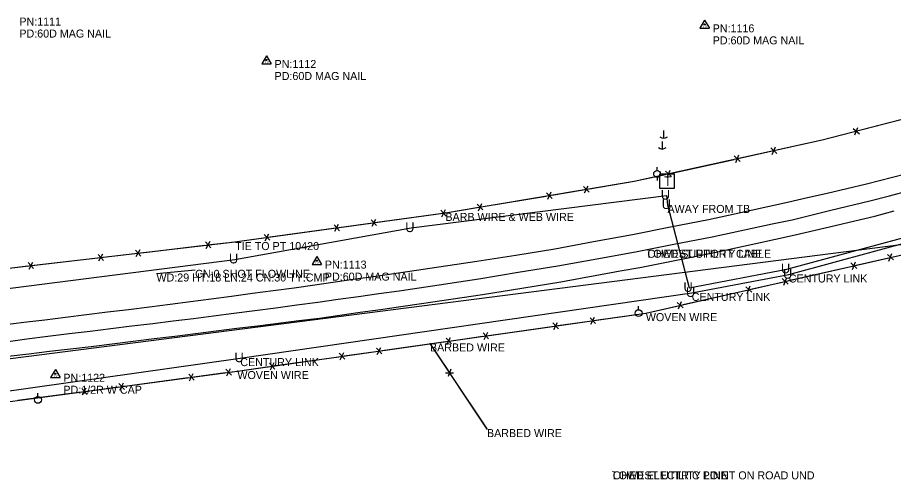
# Model space of a CAD drawing. Extents: x 1568433 to 1572450, y 731863 to 733450.
# Drawn here: x 1570751 to 1571298, y 732188 to 732476 of the extents above; entities that cross this region are included whole.
import ezdxf

# ---------------------------------------------------------------- set-up
doc = ezdxf.new("R2010")
doc.units = 0
for name, color, linetype in [('Default', 7, 'Continuous'), ('S_BASELINE', 7, 'Continuous'), ('S_CROSS_DRAIN', 7, 'Continuous'), ('S_CROSS_DRAIN_ANNOT', 7, 'Continuous'), ('S_DRG_PT_SYM', 7, 'Continuous'), ('S_EDGE_PAVEMENT', 7, 'Continuous'), ('S_ELECTRIC_UTILITIES_ANNOT', 7, 'Continuous'), ('S_FENCE', 7, 'Continuous'), ('S_FENCE_ANNOT', 7, 'Continuous'), ('S_MSC_PT_SYM', 7, 'Continuous'), ('S_PAVEMENT_CROWN', 7, 'Continuous'), ('S_SECONDARY_CTL', 7, 'Continuous'), ('S_SECONDARY_CTL_ANNOT', 7, 'Continuous'), ('S_SURVEY_TEXT_ANNOT', 7, 'Continuous'), ('S_TELEPHONE_UTILITIES', 7, 'Continuous'), ('S_UNDERGROUND_CABLE', 7, 'Continuous'), ('S_UNDERGROUND_CABLE_ANNOT', 7, 'Continuous'), ('S_UTILITY_POLE', 7, 'Continuous'), ('S_UTL_PT_SYM', 7, 'Continuous')]:
    doc.layers.add(name, color=color, linetype=linetype)

msp = doc.modelspace()

# ---------------------------------------------------------------- linework, layer by layer
at = {"layer": 'S_BASELINE'}
msp.add_line((1570488.07, 732230.45), (1571317.07, 732336.49), dxfattribs=at)
at = {"layer": 'S_CROSS_DRAIN'}
msp.add_line((1570837.86, 732316.62), (1570862.03, 732318.92), dxfattribs=at)
at = {"layer": 'S_DRG_PT_SYM'}
for points in [[(1570837.86, 732316.62), (1570837.86, 732316.67), (1570837.86, 732316.62), (1570837.81, 732316.62), (1570837.86, 732316.62), (1570837.86, 732316.57), (1570837.86, 732316.62), (1570837.91, 732316.62)], [(1570862.03, 732318.92), (1570862.03, 732318.97), (1570862.03, 732318.92), (1570861.98, 732318.92), (1570862.03, 732318.92), (1570862.03, 732318.87), (1570862.03, 732318.92), (1570862.08, 732318.92)]]:
    msp.add_lwpolyline(points, dxfattribs=at)
at = {"layer": 'S_EDGE_PAVEMENT'}
for points in [[(1570742.1, 732284.58), (1570755.11, 732286.19), (1570768.12, 732287.8), (1570781.13, 732289.41), (1570794.24, 732291.03), (1570807.35, 732292.64), (1570820.46, 732294.25), (1570833.57, 732295.86), (1570846.36, 732297.54), (1570859.16, 732299.21), (1570871.96, 732300.88), (1570884.76, 732302.56), (1570897.75, 732304.29), (1570910.75, 732306.02), (1570923.75, 732307.75), (1570936.75, 732309.48), (1570949.47, 732311.34), (1570962.19, 732313.2), (1570974.92, 732315.05), (1570987.64, 732316.91), (1571000.2, 732318.74), (1571012.76, 732320.56), (1571025.32, 732322.38), (1571037.88, 732324.21), (1571062.21, 732328.15), (1571086.55, 732332.08), (1571110.84, 732336.56), (1571135.14, 732341.04), (1571158.87, 732345.69), (1571182.6, 732350.35), (1571194.93, 732353.04), (1571207.26, 732355.74), (1571219.6, 732358.44), (1571231.93, 732361.14), (1571244.27, 732363.99), (1571256.61, 732366.84), (1571268.95, 732369.68), (1571281.29, 732372.53), (1571305.48, 732378.73)], [(1570745.24, 732265.07), (1570758.2, 732266.55), (1570771.16, 732268.04), (1570784.12, 732269.52), (1570797.21, 732271.13), (1570810.29, 732272.75), (1570823.37, 732274.36), (1570836.45, 732275.97), (1570849.37, 732277.58), (1570862.3, 732279.19), (1570875.22, 732280.79), (1570888.14, 732282.4), (1570901, 732283.99), (1570913.87, 732285.58), (1570926.73, 732287.18), (1570939.59, 732288.77), (1570952.33, 732290.59), (1570965.07, 732292.41), (1570977.81, 732294.23), (1570990.54, 732296.06), (1571003.27, 732297.92), (1571016, 732299.78), (1571028.73, 732301.65), (1571041.46, 732303.51), (1571065.9, 732307.45), (1571090.34, 732311.39), (1571102.68, 732313.66), (1571115.01, 732315.92), (1571127.35, 732318.19), (1571139.68, 732320.46), (1571163.51, 732325.17), (1571187.33, 732329.87), (1571199.67, 732332.57), (1571212.01, 732335.27), (1571224.35, 732337.97), (1571236.69, 732340.67), (1571249.12, 732343.61), (1571261.55, 732346.56), (1571273.98, 732349.5), (1571286.41, 732352.44), (1571298.54, 732355.64)]]:
    msp.add_lwpolyline(points, dxfattribs=at)
at = {"layer": 'S_FENCE'}
for p, q in [((1571253.56, 732399.93), (1571367.97, 732429.81)), ((1571272.92, 732407.11), (1571276.73, 732403.87)), ((1571272.92, 732407.11), (1571276.73, 732403.87)), ((1571273.96, 732403.14), (1571275.69, 732407.83)), ((1571273.96, 732403.14), (1571275.69, 732407.83)), ((1571136.16, 732374.14), (1571253.56, 732399.93)), ((1571221.49, 732394.98), (1571225.16, 732391.6)), ((1571221.49, 732394.98), (1571225.16, 732391.6)), ((1571222.37, 732390.98), (1571224.28, 732395.6)), ((1571222.37, 732390.98), (1571224.28, 732395.6)), ((1571198.65, 732389.96), (1571202.32, 732386.58)), ((1571198.65, 732389.96), (1571202.32, 732386.58)), ((1571199.53, 732385.96), (1571201.44, 732390.58)), ((1571199.53, 732385.96), (1571201.44, 732390.58)), ((1571156.65, 732376.54), (1571158.56, 732381.16)), ((1571156.65, 732376.54), (1571158.56, 732381.16)), ((1571155.77, 732380.54), (1571159.44, 732377.15)), ((1571155.77, 732380.54), (1571159.44, 732377.15)), ((1571018.28, 732354.41), (1571136.16, 732374.14)), ((1571104.54, 732370.92), (1571108.04, 732367.35)), ((1571104.54, 732370.92), (1571108.04, 732367.35)), ((1571105.21, 732366.88), (1571107.36, 732371.39)), ((1571105.21, 732366.88), (1571107.36, 732371.39)), ((1571081.48, 732367.06), (1571084.97, 732363.49)), ((1571081.48, 732367.06), (1571084.97, 732363.49)), ((1571082.15, 732363.02), (1571084.3, 732367.53)), ((1571082.15, 732363.02), (1571084.3, 732367.53)), ((1571038.18, 732359.82), (1571041.68, 732356.25)), ((1571038.18, 732359.82), (1571041.68, 732356.25)), ((1571038.85, 732355.78), (1571041, 732360.29)), ((1571038.85, 732355.78), (1571041, 732360.29)), ((1570885.13, 732336.24), (1571018.28, 732354.41)), ((1571015.46, 732356.09), (1571018.85, 732352.42)), ((1571015.46, 732356.09), (1571018.85, 732352.42)), ((1571016.01, 732352.03), (1571018.3, 732356.48)), ((1571016.01, 732352.03), (1571018.3, 732356.48)), ((1570971.93, 732350.15), (1570975.32, 732346.48)), ((1570971.93, 732350.15), (1570975.32, 732346.48)), ((1570972.48, 732346.09), (1570974.76, 732350.54)), ((1570972.48, 732346.09), (1570974.76, 732350.54)), ((1570948.74, 732346.99), (1570952.13, 732343.32)), ((1570948.74, 732346.99), (1570952.13, 732343.32)), ((1570949.29, 732342.93), (1570951.58, 732347.38)), ((1570949.29, 732342.93), (1570951.58, 732347.38)), ((1570905.21, 732341.05), (1570908.6, 732337.38)), ((1570905.21, 732341.05), (1570908.6, 732337.38)), ((1570905.76, 732336.99), (1570908.04, 732341.43)), ((1570905.76, 732336.99), (1570908.04, 732341.43)), ((1570603.72, 732303.31), (1570885.13, 732336.24)), ((1570868.48, 732336.35), (1570871.81, 732332.62)), ((1570868.48, 732336.35), (1570871.81, 732332.62)), ((1570868.96, 732332.29), (1570871.33, 732336.69)), ((1570868.96, 732332.29), (1570871.33, 732336.69)), ((1571143.4, 732291.89), (1571331.7, 732334.82)), ((1570801.52, 732328.52), (1570804.85, 732324.78)), ((1570801.52, 732328.52), (1570804.85, 732324.78)), ((1570802, 732324.45), (1570804.37, 732328.85)), ((1570802, 732324.45), (1570804.37, 732328.85)), ((1570824.79, 732331.24), (1570828.12, 732327.51)), ((1570824.79, 732331.24), (1570828.12, 732327.51)), ((1570825.27, 732327.17), (1570827.64, 732331.57)), ((1570825.27, 732327.17), (1570827.64, 732331.57)), ((1571294.29, 732328.39), (1571297.99, 732325.04)), ((1571294.29, 732328.39), (1571297.99, 732325.04)), ((1571295.2, 732324.4), (1571297.08, 732329.03)), ((1571295.2, 732324.4), (1571297.08, 732329.03)), ((1570757.83, 732323.41), (1570761.15, 732319.67)), ((1570757.83, 732323.41), (1570761.15, 732319.67)), ((1570758.31, 732319.34), (1570760.68, 732323.74)), ((1570758.31, 732319.34), (1570760.68, 732323.74)), ((1571271.47, 732323.19), (1571275.17, 732319.83)), ((1571271.47, 732323.19), (1571275.17, 732319.83)), ((1571272.38, 732319.2), (1571274.26, 732323.83)), ((1571272.38, 732319.2), (1571274.26, 732323.83)), ((1571228.63, 732313.42), (1571232.33, 732310.06)), ((1571228.63, 732313.42), (1571232.33, 732310.06)), ((1571229.54, 732309.43), (1571231.42, 732314.06)), ((1571229.54, 732309.43), (1571231.42, 732314.06)), ((1571205.81, 732308.22), (1571209.51, 732304.86)), ((1571205.81, 732308.22), (1571209.51, 732304.86)), ((1571206.72, 732304.22), (1571208.6, 732308.85)), ((1571206.72, 732304.22), (1571208.6, 732308.85)), ((1571163.88, 732294.46), (1571165.76, 732299.09)), ((1571163.88, 732294.46), (1571165.76, 732299.09)), ((1571162.97, 732298.45), (1571166.67, 732295.09)), ((1571162.97, 732298.45), (1571166.67, 732295.09)), ((1570888.4, 732255.74), (1571143.4, 732291.89)), ((1571108.58, 732289.02), (1571111.99, 732285.36)), ((1571108.58, 732289.02), (1571111.99, 732285.36)), ((1571109.15, 732284.96), (1571111.41, 732289.42)), ((1571109.15, 732284.96), (1571111.41, 732289.42)), ((1571085.39, 732285.73), (1571088.81, 732282.08)), ((1571085.39, 732285.73), (1571088.81, 732282.08)), ((1571085.97, 732281.68), (1571088.23, 732286.13)), ((1571085.97, 732281.68), (1571088.23, 732286.13)), ((1571041.87, 732279.56), (1571045.28, 732275.91)), ((1571041.87, 732279.56), (1571045.28, 732275.91)), ((1571042.44, 732275.51), (1571044.71, 732279.96)), ((1571042.44, 732275.51), (1571044.71, 732279.96)), ((1571008.64, 732272.95), (1571044.24, 732219.52)), ((1571018.69, 732276.28), (1571022.1, 732272.62)), ((1571018.69, 732276.28), (1571022.1, 732272.62)), ((1571019.26, 732272.22), (1571021.52, 732276.68)), ((1571019.26, 732272.22), (1571021.52, 732276.68)), ((1570951.98, 732266.82), (1570955.39, 732263.17)), ((1570951.98, 732266.82), (1570955.39, 732263.17)), ((1570952.55, 732262.76), (1570954.82, 732267.22)), ((1570952.55, 732262.76), (1570954.82, 732267.22)), ((1570975.16, 732270.11), (1570978.57, 732266.45)), ((1570975.16, 732270.11), (1570978.57, 732266.45)), ((1570975.74, 732266.05), (1570978, 732270.51)), ((1570975.74, 732266.05), (1570978, 732270.51)), ((1570908.45, 732260.65), (1570911.87, 732257)), ((1570908.45, 732260.65), (1570911.87, 732257)), ((1570909.03, 732256.59), (1570911.29, 732261.05)), ((1570909.03, 732256.59), (1570911.29, 732261.05)), ((1570593.81, 732216.49), (1570888.4, 732255.74)), ((1570881.28, 732256.86), (1570884.66, 732253.18)), ((1570881.28, 732256.86), (1570884.66, 732253.18)), ((1570881.82, 732252.8), (1570884.12, 732257.24)), ((1570881.82, 732252.8), (1570884.12, 732257.24)), ((1571021.74, 732256.97), (1571019.92, 732252.31)), ((1571021.74, 732256.97), (1571019.92, 732252.31)), ((1570858.05, 732253.76), (1570861.44, 732250.08)), ((1570858.05, 732253.76), (1570861.44, 732250.08)), ((1570858.59, 732249.7), (1570860.89, 732254.14)), ((1570858.59, 732249.7), (1570860.89, 732254.14)), ((1571018.33, 732254.7), (1571023.33, 732254.58)), ((1571018.33, 732254.7), (1571023.33, 732254.58)), ((1570791.21, 732244.86), (1570794.6, 732241.17)), ((1570791.21, 732244.86), (1570794.6, 732241.17)), ((1570791.75, 732240.8), (1570794.05, 732245.23)), ((1570791.75, 732240.8), (1570794.05, 732245.23)), ((1570814.44, 732247.95), (1570817.82, 732244.27)), ((1570814.44, 732247.95), (1570817.82, 732244.27)), ((1570814.98, 732243.89), (1570817.28, 732248.33)), ((1570814.98, 732243.89), (1570817.28, 732248.33))]:
    msp.add_line(p, q, dxfattribs=at)
for points in [[(1571276.76, 732405.99), (1571315.43, 732416.09)], [(1571276.76, 732405.99), (1571315.43, 732416.09)], [(1571253.56, 732399.93), (1571272.89, 732404.98)], [(1571253.56, 732399.93), (1571272.89, 732404.98)], [(1571225.27, 732393.72), (1571253.56, 732399.93)], [(1571225.27, 732393.72), (1571253.56, 732399.93)], [(1571201.88, 732388.58), (1571221.38, 732392.86)], [(1571201.88, 732388.58), (1571221.38, 732392.86)], [(1571159.55, 732379.28), (1571198.54, 732387.84)], [(1571159.55, 732379.28), (1571198.54, 732387.84)], [(1571136.16, 732374.14), (1571155.65, 732378.42)], [(1571136.16, 732374.14), (1571155.65, 732378.42)], [(1571108.25, 732369.47), (1571136.16, 732374.14)], [(1571108.25, 732369.47), (1571136.16, 732374.14)], [(1571041.89, 732358.36), (1571081.26, 732364.95)], [(1571041.89, 732358.36), (1571081.26, 732364.95)], [(1571084.64, 732365.51), (1571104.32, 732368.81)], [(1571084.64, 732365.51), (1571104.32, 732368.81)], [(1570975.6, 732348.59), (1571015.18, 732353.99)], [(1570975.6, 732348.59), (1571015.18, 732353.99)], [(1571018.28, 732354.41), (1571037.96, 732357.7)], [(1571018.28, 732354.41), (1571037.96, 732357.7)], [(1570908.88, 732339.48), (1570948.46, 732344.88)], [(1570908.88, 732339.48), (1570948.46, 732344.88)], [(1570951.85, 732345.35), (1570971.64, 732348.05)], [(1570951.85, 732345.35), (1570971.64, 732348.05)], [(1570885.13, 732336.24), (1570904.92, 732338.94)], [(1570885.13, 732336.24), (1570904.92, 732338.94)], [(1570828.44, 732329.61), (1570868.16, 732334.25)], [(1570828.44, 732329.61), (1570868.16, 732334.25)], [(1570871.57, 732334.65), (1570885.13, 732336.24)], [(1570871.57, 732334.65), (1570885.13, 732336.24)], [(1570761.48, 732321.77), (1570801.2, 732326.42)], [(1570761.48, 732321.77), (1570801.2, 732326.42)], [(1570804.61, 732326.82), (1570824.47, 732329.14)], [(1570804.61, 732326.82), (1570824.47, 732329.14)], [(1571274.72, 732321.83), (1571294.19, 732326.27)], [(1571274.72, 732321.83), (1571294.19, 732326.27)], [(1570737.65, 732318.98), (1570757.51, 732321.31)], [(1570737.65, 732318.98), (1570757.51, 732321.31)], [(1571232.43, 732312.19), (1571271.37, 732321.07)], [(1571232.43, 732312.19), (1571271.37, 732321.07)], [(1571209.06, 732306.86), (1571228.53, 732311.3)], [(1571209.06, 732306.86), (1571228.53, 732311.3)], [(1571166.77, 732297.21), (1571205.72, 732306.1)], [(1571166.77, 732297.21), (1571205.72, 732306.1)], [(1571143.4, 732291.89), (1571162.87, 732296.33)], [(1571143.4, 732291.89), (1571162.87, 732296.33)], [(1571112.26, 732287.47), (1571143.4, 732291.89)], [(1571112.26, 732287.47), (1571143.4, 732291.89)], [(1571045.55, 732278.02), (1571085.12, 732283.62)], [(1571045.55, 732278.02), (1571085.12, 732283.62)], [(1571088.52, 732284.11), (1571108.3, 732286.91)], [(1571088.52, 732284.11), (1571108.3, 732286.91)], [(1571021.81, 732274.65), (1571041.6, 732277.45)], [(1571021.81, 732274.65), (1571041.6, 732277.45)], [(1570978.85, 732268.56), (1571018.41, 732274.17)], [(1570978.85, 732268.56), (1571018.41, 732274.17)], [(1571008.64, 732272.95), (1571019.72, 732256.31)], [(1571008.64, 732272.95), (1571019.72, 732256.31)], [(1570955.1, 732265.19), (1570974.89, 732268)], [(1570955.1, 732265.19), (1570974.89, 732268)], [(1570912.14, 732259.1), (1570951.71, 732264.71)], [(1570912.14, 732259.1), (1570951.71, 732264.71)], [(1570884.95, 732255.28), (1570888.4, 732255.74)], [(1570884.95, 732255.28), (1570888.4, 732255.74)], [(1570888.4, 732255.74), (1570908.18, 732258.54)], [(1570888.4, 732255.74), (1570908.18, 732258.54)], [(1570818.11, 732246.37), (1570857.76, 732251.66)], [(1570818.11, 732246.37), (1570857.76, 732251.66)], [(1570861.17, 732252.11), (1570880.99, 732254.75)], [(1570861.17, 732252.11), (1570880.99, 732254.75)], [(1571021.94, 732252.98), (1571044.12, 732219.7)], [(1571021.94, 732252.98), (1571044.12, 732219.7)], [(1570794.33, 732243.2), (1570814.15, 732245.85)], [(1570794.33, 732243.2), (1570814.15, 732245.85)], [(1570751.27, 732237.47), (1570790.92, 732242.75)], [(1570751.27, 732237.47), (1570790.92, 732242.75)]]:
    msp.add_lwpolyline(points, dxfattribs=at)
at = {"layer": 'S_MSC_PT_SYM'}
for points in [[(1571253.56, 732399.93), (1571253.56, 732399.98), (1571253.56, 732399.93), (1571253.51, 732399.93), (1571253.56, 732399.93), (1571253.56, 732399.88), (1571253.56, 732399.93), (1571253.61, 732399.93)], [(1571136.16, 732374.14), (1571136.16, 732374.19), (1571136.16, 732374.14), (1571136.11, 732374.14), (1571136.16, 732374.14), (1571136.16, 732374.09), (1571136.16, 732374.14), (1571136.21, 732374.14)], [(1571018.28, 732354.41), (1571018.28, 732354.46), (1571018.28, 732354.41), (1571018.23, 732354.41), (1571018.28, 732354.41), (1571018.28, 732354.36), (1571018.28, 732354.41), (1571018.33, 732354.41)], [(1570885.13, 732336.24), (1570885.13, 732336.29), (1570885.13, 732336.24), (1570885.08, 732336.24), (1570885.13, 732336.24), (1570885.13, 732336.19), (1570885.13, 732336.24), (1570885.18, 732336.24)], [(1571144.36, 732331.44), (1571144.36, 732331.49), (1571144.36, 732331.44), (1571144.31, 732331.44), (1571144.36, 732331.44), (1571144.36, 732331.39), (1571144.36, 732331.44), (1571144.41, 732331.44)], [(1571143.4, 732291.89), (1571143.4, 732291.94), (1571143.4, 732291.89), (1571143.35, 732291.89), (1571143.4, 732291.89), (1571143.4, 732291.84), (1571143.4, 732291.89), (1571143.45, 732291.89)], [(1571008.64, 732272.95), (1571008.64, 732273), (1571008.64, 732272.95), (1571008.59, 732272.95), (1571008.64, 732272.95), (1571008.64, 732272.9), (1571008.64, 732272.95), (1571008.69, 732272.95)], [(1570888.4, 732255.74), (1570888.4, 732255.79), (1570888.4, 732255.74), (1570888.35, 732255.74), (1570888.4, 732255.74), (1570888.4, 732255.69), (1570888.4, 732255.74), (1570888.45, 732255.74)], [(1571044.24, 732219.52), (1571044.24, 732219.57), (1571044.24, 732219.52), (1571044.19, 732219.52), (1571044.24, 732219.52), (1571044.24, 732219.47), (1571044.24, 732219.52), (1571044.29, 732219.52)], [(1571122.8, 732193.14), (1571122.8, 732193.19), (1571122.8, 732193.14), (1571122.75, 732193.14), (1571122.8, 732193.14), (1571122.8, 732193.09), (1571122.8, 732193.14), (1571122.85, 732193.14)]]:
    msp.add_lwpolyline(points, dxfattribs=at)
at = {"layer": 'S_PAVEMENT_CROWN'}
msp.add_lwpolyline([(1570743.76, 732274.07), (1570756.94, 732275.76), (1570770.12, 732277.46), (1570783.3, 732279.16), (1570796.4, 732280.72), (1570809.49, 732282.29), (1570822.59, 732283.86), (1570835.68, 732285.42), (1570848.31, 732287.02), (1570860.95, 732288.62), (1570873.58, 732290.23), (1570886.21, 732291.83), (1570899.33, 732293.55), (1570912.45, 732295.28), (1570925.57, 732297), (1570938.69, 732298.73), (1570951.39, 732300.51), (1570964.09, 732302.29), (1570976.78, 732304.07), (1570989.48, 732305.84), (1571001.91, 732307.71), (1571014.34, 732309.58), (1571026.76, 732311.45), (1571039.19, 732313.32), (1571063.81, 732317.37), (1571088.43, 732321.42), (1571112.74, 732325.82), (1571137.05, 732330.22), (1571160.97, 732334.85), (1571184.9, 732339.47), (1571197.35, 732342.15), (1571209.81, 732344.84), (1571222.27, 732347.53), (1571234.72, 732350.21), (1571259, 732356.09), (1571283.28, 732361.98), (1571295.61, 732365.17), (1571307.93, 732368.35)], dxfattribs=at)
at = {"layer": 'S_SECONDARY_CTL'}
for p, q in [((1571180.15, 732474.71), (1571177.14, 732469.76)), ((1571180.15, 732474.71), (1571183.1, 732469.76)), ((1571177.14, 732469.76), (1571183.1, 732469.76)), ((1570906.62, 732452.47), (1570903.61, 732447.51)), ((1570906.62, 732452.47), (1570909.56, 732447.51)), ((1570903.61, 732447.51), (1570909.56, 732447.51)), ((1570938.03, 732327.28), (1570935.02, 732322.33)), ((1570938.03, 732327.28), (1570940.98, 732322.33)), ((1570935.02, 732322.33), (1570940.98, 732322.33)), ((1570774.74, 732256.66), (1570771.73, 732251.71)), ((1570774.74, 732256.66), (1570777.68, 732251.71)), ((1570771.73, 732251.71), (1570777.68, 732251.71))]:
    msp.add_line(p, q, dxfattribs=at)
for centre, radius in [((1571180.15, 732472.1), 0.311), ((1571180.15, 732472.1), 0.183), ((1571180.15, 732472.1), 0.103), ((1570906.62, 732449.86), 0.311), ((1570906.62, 732449.86), 0.183), ((1570906.62, 732449.86), 0.103), ((1570938.03, 732324.67), 0.311), ((1570938.03, 732324.67), 0.183), ((1570938.03, 732324.67), 0.103), ((1570774.74, 732254.05), 0.311), ((1570774.74, 732254.05), 0.183), ((1570774.74, 732254.05), 0.103)]:
    msp.add_circle(centre, radius, dxfattribs=at)
at = {"layer": 'S_TELEPHONE_UTILITIES'}
msp.add_lwpolyline([(1571152.13, 732369.75), (1571152.13, 732378.75), (1571161.13, 732378.75), (1571161.13, 732369.75)], close=True, dxfattribs=at)
at = {"layer": 'S_UNDERGROUND_CABLE'}
for p, q in [((1570996.82, 732345.02), (1571156.37, 732365.31)), ((1571156.37, 732365.31), (1571156.92, 732359.42)), ((1571156.92, 732359.42), (1571170.55, 732307.72)), ((1570886.76, 732325.45), (1570996.82, 732345.02)), ((1571231.42, 732319.3), (1571327.78, 732345.29)), ((1571232.71, 732316), (1571328.28, 732342.13)), ((1570580.49, 732286.26), (1570886.76, 732325.45)), ((1571170.55, 732307.72), (1571231.42, 732319.3)), ((1571172.09, 732304.54), (1571232.71, 732316)), ((1570890.22, 732263.81), (1571172.09, 732304.54)), ((1570624.71, 732226.07), (1570890.22, 732263.81))]:
    msp.add_line(p, q, dxfattribs=at)
at = {"layer": 'S_UTILITY_POLE'}
for p, q in [((1571154.49, 732405.77), (1571154.49, 732401.04)), ((1571153.64, 732399), (1571153.64, 732394.27)), ((1571150.41, 732380.85), (1571150.41, 732382.98)), ((1571150.41, 732376.63), (1571150.41, 732374.57)), ((1571138.8, 732294.03), (1571138.8, 732296.14)), ((1570763.77, 732239.87), (1570763.77, 732241.98))]:
    msp.add_line(p, q, dxfattribs=at)
for centre, radius in [((1571150.43, 732378.77), 2.11), ((1571138.92, 732291.89), 2.13), ((1570763.89, 732237.73), 2.13)]:
    msp.add_circle(centre, radius, dxfattribs=at)
for centre in [(1571154.55, 732404.46), (1571153.71, 732397.7)]:
    msp.add_arc(centre, 3.41, 226.3972, 313.6028, dxfattribs=at)
at = {"layer": 'S_UTL_PT_SYM'}
for points in [[(1571144.36, 732331.44), (1571144.36, 732331.49), (1571144.36, 732331.44), (1571144.31, 732331.44), (1571144.36, 732331.44), (1571144.36, 732331.39), (1571144.36, 732331.44), (1571144.41, 732331.44)], [(1571122.8, 732193.14), (1571122.8, 732193.19), (1571122.8, 732193.14), (1571122.75, 732193.14), (1571122.8, 732193.14), (1571122.8, 732193.09), (1571122.8, 732193.14), (1571122.85, 732193.14)]]:
    msp.add_lwpolyline(points, dxfattribs=at)

# ---------------------------------------------------------------- texts
at = {"layer": 'Default'}
for p in [(1571152.74, 732362.77), (1571153.29, 732356.88), (1570993.19, 732342.47), (1570883.13, 732322.91), (1571227.79, 732316.75), (1571229.08, 732313.46), (1571166.92, 732305.17), (1571168.46, 732302), (1570886.59, 732261.27)]:
    msp.add_text('U', height=6, dxfattribs=at).set_placement(p)
at = {"layer": 'S_CROSS_DRAIN_ANNOT'}
for s, p in [('WD:29 HT:18 LN:24 CN:30 TY:CMP', (1570837.86, 732311.62)), ('CN:0 SHOT FLOWLINE', (1570862.03, 732313.92))]:
    msp.add_text(s, height=5, dxfattribs=at).set_placement(p)
at = {"layer": 'S_ELECTRIC_UTILITIES_ANNOT'}
for p in [(1571144.36, 732326.44), (1571122.8, 732188.14)]:
    msp.add_text('LOWEST UTILITY LINE', height=5, dxfattribs=at).set_placement(p)
at = {"layer": 'S_FENCE_ANNOT'}
for s, p in [('BARB WIRE & WEB WIRE', (1571018.28, 732349.41)), (' TIE TO PT 10420', (1570885.13, 732331.24)), ('WOVEN WIRE', (1571143.4, 732286.89)), ('BARBED WIRE', (1571008.64, 732267.95)), ('WOVEN WIRE', (1570888.4, 732250.74)), ('BARBED WIRE', (1571044.24, 732214.52))]:
    msp.add_text(s, height=5, dxfattribs=at).set_placement(p)
at = {"layer": 'S_SECONDARY_CTL'}
for p in [(1571178.95, 732470.09), (1570905.41, 732447.84), (1570936.82, 732322.66), (1570773.53, 732252.04)]:
    msp.add_text('TV', height=1.5, dxfattribs=at).set_placement(p)
at = {"layer": 'S_SECONDARY_CTL_ANNOT'}
for s, p in [('PN:1111', (1570752.28, 732471.36)), ('PD:60D MAG NAIL', (1570752.28, 732463.86)), ('PN:1116', (1571185.15, 732467.1)), ('PD:60D MAG NAIL', (1571185.15, 732459.6)), ('PN:1112', (1570911.62, 732444.86)), ('PD:60D MAG NAIL', (1570911.62, 732437.36)), ('PN:1113', (1570943.03, 732319.67)), ('PD:60D MAG NAIL', (1570943.03, 732312.17)), ('PN:1122', (1570779.74, 732249.05)), ('PD:1/2R W CAP', (1570779.74, 732241.55))]:
    msp.add_text(s, height=5, dxfattribs=at).set_placement(p)
at = {"layer": 'S_SURVEY_TEXT_ANNOT'}
for s, p in [('OHED SUPPORT CABLE', (1571144.36, 732326.44)), ('OHED ELECTRIC POINT ON ROAD UND', (1571122.8, 732188.14))]:
    msp.add_text(s, height=5, dxfattribs=at).set_placement(p)
at = {"layer": 'S_TELEPHONE_UTILITIES'}
msp.add_text('T', height=6, dxfattribs=at).set_placement((1571154.69, 732371.25))
at = {"layer": 'S_UNDERGROUND_CABLE_ANNOT'}
for s, p in [('AWAY FROM TB', (1571156.92, 732354.42)), ('CENTURY LINK', (1571232.71, 732311)), ('CENTURY LINK', (1571172.09, 732299.54)), ('CENTURY LINK', (1570890.22, 732258.81))]:
    msp.add_text(s, height=5, dxfattribs=at).set_placement(p)

doc.saveas('drawing.dxf')
